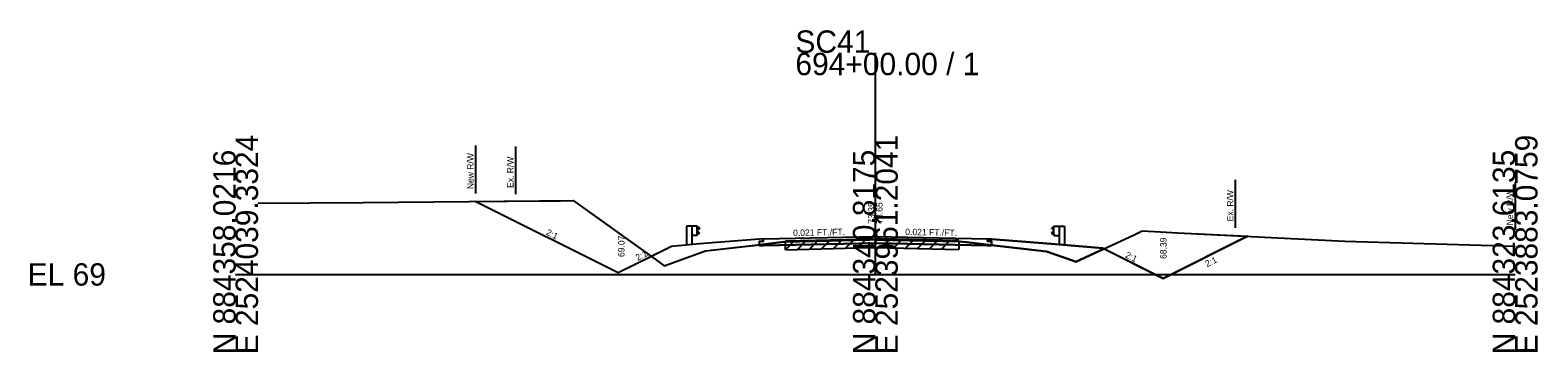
# Model space of a CAD drawing. Extents: x -26 to 183, y -10 to 24021.
# Drawn here: x -25.7 to 162.8, y 18990.3 to 19030.6 of the extents above; entities that cross this region are included whole.
import ezdxf

# ---------------------------------------------------------------- set-up
doc = ezdxf.new("R2010")
doc.units = 0
for name, color, linetype in [('RD_GPK_XS_Cell', 7, 'Continuous'), ('RD_XS_Base', 7, 'Continuous'), ('RD_XS_Buildup', 7, 'Continuous'), ('RD_XS_EarthShd', 7, 'Continuous'), ('RD_XS_EwShp', 7, 'Continuous'), ('RD_XS_ExGround', 7, 'Continuous'), ('RD_XS_ExPaveRet', 7, 'Continuous'), ('RD_XS_ExRW', 7, 'Continuous'), ('RD_XS_GR', 7, 'Continuous'), ('RD_XS_NewRW', 7, 'Continuous'), ('RD_XS_Pave', 7, 'Continuous'), ('RD_XS_TieSlope', 7, 'Continuous'), ('RD_XS_TX_Elev_EX', 7, 'Continuous'), ('RD_XS_TX_Elev_PR', 7, 'Continuous'), ('RD_XS_TX_Slope', 7, 'Continuous')]:
    doc.layers.add(name, color=color, linetype=linetype)

msp = doc.modelspace()

# ---------------------------------------------------------------- linework, layer by layer
at = {"layer": 'RD_GPK_XS_Cell'}
for p, q in [((80, 19000), (80, 19027.74)), ((0, 19000), (80, 19000)), ((80, 19000), (160, 19000))]:
    msp.add_line(p, q, dxfattribs=at)
at = {"layer": 'RD_XS_Base'}
for p in [(66.01, 19003.63), (93.99, 19003.63)]:
    msp.add_line(p, (80, 19003.92), dxfattribs=at)
at = {"layer": 'RD_XS_Buildup'}
for p, q in [((68.76, 19004.21), (80, 19004.44)), ((68.76, 19004.09), (68.76, 19004.21)), ((90.44, 19004.23), (80, 19004.44)), ((90.44, 19004.13), (90.44, 19004.23))]:
    msp.add_line(p, q, dxfattribs=at)
at = {"layer": 'RD_XS_EarthShd'}
for p, q in [((66, 19004.47), (58, 19003.81)), ((94, 19004.47), (102, 19003.81)), ((58, 19003.81), (54.5, 19003.51)), ((102, 19003.81), (108.45, 19003.27))]:
    msp.add_line(p, q, dxfattribs=at)
at = {"layer": 'RD_XS_EwShp'}
for points in [[(37.99, 19009.2), (40.63, 19009.23), (42.2, 19009.25), (52, 19002.26), (47.83, 19000.18), (29.94, 19009.13)], [(40.63, 19009.23), (42.2, 19009.25), (52, 19002.26), (47.83, 19000.18), (29.94, 19009.13), (37.99, 19009.2)], [(40.63, 19009.23), (42.2, 19009.25), (52, 19002.26), (47.83, 19000.18), (29.94, 19009.13), (37.99, 19009.2)], [(54.5, 19003.51), (52, 19002.26), (52.94, 19001.59), (53.6, 19001.07), (58.76, 19002.95), (65.5, 19003.72), (65.5, 19004.17), (66, 19004.18), (66, 19004.47), (58, 19003.81)], [(54.5, 19003.51), (52, 19002.26), (52.94, 19001.59), (53.6, 19001.07), (58.76, 19002.95), (65.5, 19003.72), (65.5, 19004.17), (66, 19004.18), (66, 19004.47), (58, 19003.81)], [(54.5, 19003.51), (52, 19002.26), (52.94, 19001.59), (53.6, 19001.07), (58.76, 19002.95), (65.5, 19003.72), (65.5, 19004.17), (66, 19004.18), (66, 19004.47), (58, 19003.81)], [(66.01, 19003.63), (80, 19003.92), (93.99, 19003.63), (94.5, 19003.62), (94.5, 19003.67), (91.4, 19004.03), (90.44, 19004.13), (80.12, 19004.35), (79.71, 19004.36), (79.28, 19004.35), (68.76, 19004.09), (68.2, 19004.03), (65.5, 19003.72), (65.5, 19003.62)], [(68.76, 19004.09), (79.28, 19004.35), (79.71, 19004.36), (80.12, 19004.35), (90.44, 19004.13), (91.4, 19004.03), (94.5, 19003.67), (94.5, 19003.62), (93.99, 19003.63), (80, 19003.92), (66.01, 19003.63), (65.5, 19003.62), (65.5, 19003.72), (68.2, 19004.03)], [(68.76, 19004.09), (79.28, 19004.35), (79.71, 19004.36), (80.12, 19004.35), (90.44, 19004.13), (91.4, 19004.03), (94.5, 19003.67), (94.5, 19003.62), (93.99, 19003.63), (80, 19003.92), (66.01, 19003.63), (65.5, 19003.62), (65.5, 19003.72), (68.2, 19004.03)], [(101.39, 19002.86), (104.63, 19001.73), (105.05, 19001.59), (108.58, 19003.2), (108.45, 19003.27), (102, 19003.81), (94, 19004.47), (94, 19004.18), (94.5, 19004.17), (94.5, 19003.67)], [(94, 19004.18), (94, 19004.47), (102, 19003.81), (108.45, 19003.27), (108.58, 19003.2), (105.05, 19001.59), (104.63, 19001.73), (101.39, 19002.86), (94.5, 19003.67), (94.5, 19004.17)], [(94, 19004.18), (94, 19004.47), (102, 19003.81), (108.45, 19003.27), (108.58, 19003.2), (105.05, 19001.59), (104.63, 19001.73), (101.39, 19002.86), (94.5, 19003.67), (94.5, 19004.17)], [(115.64, 19005.35), (117.79, 19005.22), (126.53, 19004.77), (115.99, 18999.5), (108.58, 19003.2), (112.35, 19004.94), (113.38, 19005.45)], [(113.38, 19005.45), (115.64, 19005.35), (117.79, 19005.22), (126.53, 19004.77), (115.99, 18999.5), (108.58, 19003.2), (112.35, 19004.94)], [(113.38, 19005.45), (115.64, 19005.35), (117.79, 19005.22), (126.53, 19004.77), (115.99, 18999.5), (108.58, 19003.2), (112.35, 19004.94)]]:
    msp.add_lwpolyline(points, close=True, dxfattribs=at)
at = {"layer": 'RD_XS_ExGround'}
for p, q in [((2.78, 19008.92), (15.94, 19008.99)), ((15.94, 19008.99), (37.99, 19009.2)), ((37.99, 19009.2), (40.63, 19009.23)), ((40.63, 19009.23), (42.2, 19009.25)), ((42.2, 19009.25), (52.94, 19001.59)), ((68.2, 19004.03), (68.76, 19004.09)), ((68.76, 19004.09), (79.28, 19004.35)), ((79.28, 19004.35), (79.71, 19004.36)), ((79.71, 19004.36), (80.12, 19004.35)), ((80.12, 19004.35), (90.44, 19004.13)), ((90.44, 19004.13), (91.4, 19004.03)), ((105.05, 19001.59), (112.35, 19004.94)), ((112.35, 19004.94), (113.38, 19005.45)), ((113.38, 19005.45), (115.64, 19005.35)), ((115.64, 19005.35), (117.79, 19005.22)), ((117.79, 19005.22), (138.69, 19004.15)), ((138.69, 19004.15), (160, 19003.54)), ((53.6, 19001.07), (58.76, 19002.95)), ((58.76, 19002.95), (68.2, 19004.03)), ((91.4, 19004.03), (101.39, 19002.86)), ((101.39, 19002.86), (104.63, 19001.73)), ((52.94, 19001.59), (53.6, 19001.07)), ((104.63, 19001.73), (105.05, 19001.59))]:
    msp.add_line(p, q, dxfattribs=at)
at = {"layer": 'RD_XS_ExPaveRet'}
for p, q in [((68.76, 19003.09), (69.78, 19004.11)), ((68.76, 19003.09), (68.76, 19004.09)), ((70.26, 19003.12), (71.28, 19004.15)), ((71.76, 19003.16), (72.78, 19004.19)), ((73.26, 19003.2), (74.28, 19004.22)), ((74.76, 19003.24), (75.78, 19004.26)), ((76.26, 19003.27), (77.28, 19004.3)), ((77.76, 19003.31), (78.78, 19004.33)), ((79.26, 19003.35), (80.26, 19004.35)), ((80.76, 19003.33), (81.74, 19004.31)), ((82.26, 19003.3), (83.24, 19004.28)), ((83.76, 19003.27), (84.74, 19004.25)), ((85.26, 19003.24), (86.24, 19004.22)), ((86.76, 19003.21), (87.74, 19004.19)), ((88.26, 19003.18), (89.24, 19004.15)), ((90.44, 19004.13), (90.44, 19003.13)), ((68.76, 19003.09), (79.28, 19003.35)), ((79.28, 19003.35), (79.71, 19003.36)), ((79.71, 19003.36), (80.12, 19003.35)), ((80.12, 19003.35), (90.44, 19003.13))]:
    msp.add_line(p, q, dxfattribs=at)
at = {"layer": 'RD_XS_ExRW'}
for p, q in [((35, 19016.03), (35, 19010.03)), ((125, 19011.85), (125, 19005.85))]:
    msp.add_line(p, q, dxfattribs=at)
at = {"layer": 'RD_XS_GR'}
for p, q in [((56.4, 19006.06), (56.4, 19003.67)), ((57.06, 19006.06), (56.4, 19006.06)), ((57.06, 19006.06), (57.06, 19003.73)), ((57.73, 19006.06), (57.06, 19006.06)), ((57.73, 19004.89), (57.73, 19006.06)), ((57.73, 19005.98), (58, 19005.78)), ((102.32, 19005.98), (102.05, 19005.78)), ((102.32, 19006.05), (102.99, 19006.05)), ((102.32, 19004.88), (102.32, 19006.05)), ((102.99, 19006.05), (102.99, 19003.72)), ((102.99, 19006.05), (103.66, 19006.05)), ((103.66, 19006.05), (103.66, 19003.67)), ((57.73, 19004.89), (57.06, 19004.89)), ((58, 19005.73), (57.73, 19005.53)), ((58, 19005.21), (57.73, 19005.41)), ((57.73, 19004.96), (58, 19005.16)), ((58, 19005.78), (58, 19005.73)), ((58, 19005.16), (58, 19005.21)), ((102.05, 19005.73), (102.05, 19005.78)), ((102.05, 19005.73), (102.32, 19005.53)), ((102.05, 19005.21), (102.32, 19005.41)), ((102.05, 19005.21), (102.05, 19005.16)), ((102.32, 19004.96), (102.05, 19005.16)), ((102.32, 19004.88), (102.99, 19004.88))]:
    msp.add_line(p, q, dxfattribs=at)
at = {"layer": 'RD_XS_NewRW'}
for p, q in [((30, 19016.13), (30, 19010.13)), ((160, 19011.6), (160, 19005.6))]:
    msp.add_line(p, q, dxfattribs=at)
at = {"layer": 'RD_XS_Pave'}
for p, q in [((65.5, 19004.17), (66, 19004.18)), ((65.5, 19003.62), (65.5, 19004.17)), ((66, 19004.47), (80, 19004.76)), ((66, 19004.18), (66, 19004.47)), ((80, 19004.76), (94, 19004.47)), ((94, 19004.18), (94, 19004.47)), ((94.5, 19004.17), (94, 19004.18)), ((94.5, 19003.62), (94.5, 19004.17)), ((65.5, 19003.62), (66.01, 19003.63)), ((94.5, 19003.62), (93.99, 19003.63))]:
    msp.add_line(p, q, dxfattribs=at)
at = {"layer": 'RD_XS_TieSlope'}
for p, q in [((47.83, 19000.18), (29.94, 19009.13)), ((115.99, 18999.5), (126.53, 19004.77)), ((54.5, 19003.51), (47.83, 19000.18)), ((108.45, 19003.27), (115.99, 18999.5))]:
    msp.add_line(p, q, dxfattribs=at)

# ---------------------------------------------------------------- texts
at = {"layer": 'RD_GPK_XS_Cell'}
for s, p in [('SC41', (70, 19027.74)), ('694+00.00 / 1', (70, 19024.94)), ('EL 69', (-26, 18998.6))]:
    msp.add_text(s, height=2.8, dxfattribs=at).set_placement(p)
for s, p in [('E 2524039.3324', (2.8, 18990)), ('E 2523961.2041', (82.8, 18990)), ('E 2523883.0759', (162.8, 18990)), ('N 884358.0216', (0, 18990)), ('N 884340.8175', (80, 18990)), ('N 884323.6135', (160, 18990))]:
    msp.add_text(s, height=2.8, rotation=90, dxfattribs=at).set_placement(p)
at = {"layer": 'RD_XS_ExRW'}
for p in [(34.75, 19010.82), (124.75, 19006.64)]:
    msp.add_text('Ex. R/W ', height=0.8, rotation=90, dxfattribs=at).set_placement(p)
at = {"layer": 'RD_XS_NewRW'}
for p in [(29.75, 19010.67), (159.75, 19006.14)]:
    msp.add_text('New R/W ', height=0.8, rotation=90, dxfattribs=at).set_placement(p)
at = {"layer": 'RD_XS_TX_Elev_EX'}
msp.add_text('73.35', height=0.8, rotation=90, dxfattribs=at).set_placement((79.9, 19006.35))
at = {"layer": 'RD_XS_TX_Elev_PR'}
for s, p in [('73.65', (80.9, 19006.35)), ('69.07', (48.63, 19002.18)), ('68.39', (116.41, 19001.94))]:
    msp.add_text(s, height=0.8, rotation=90, dxfattribs=at).set_placement(p)
at = {"layer": 'RD_XS_TX_Slope'}
for s, rotation, p in [('2:1', 333.4349, (38.74, 19005.01)), ('0.021 FT./FT.', 1.1916, (69.72, 19004.8)), ('0.021 FT./FT.', 358.8084, (83.73, 19004.94)), ('2:1', 26.5651, (50.27, 19001.68)), ('2:1', 333.4349, (111.16, 19002.17)), ('2:1', 26.5651, (121.48, 19000.9))]:
    msp.add_text(s, height=0.8, rotation=rotation, dxfattribs=at).set_placement(p)

doc.saveas('drawing.dxf')
